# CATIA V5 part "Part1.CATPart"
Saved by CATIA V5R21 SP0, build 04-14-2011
Part number: Part1
Bounding box of the stored display mesh (mm): x -50 to 50, y -25 to 25, z -25 to 25
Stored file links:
  D:\CATIA V5R21 E-RESOURCES\CATIA-V5R21\catia-v5r21-prt\c16-catia-v5r20-prt\Sperical Joint-(Fig16-27)\CAT_V5R21_Part1.CATPart
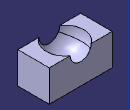
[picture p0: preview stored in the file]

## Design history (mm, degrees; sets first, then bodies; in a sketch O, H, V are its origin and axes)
Body1 (main body)
  Sketch1 on xy-plane, origin (0, 0, 0), H (1, 0, 0), V (0, 1, 0)
    line L1 (50, 25) -> (50, -25)
    line L2 (50, -25) -> (-50, -25)
    line L3 (-50, -25) -> (-50, 25)
    line L4 (-50, 25) -> (50, 25)
    length L4 = 100
    length L1 = 50
    vertical: L1 V, L3 V
    horizontal: L2 H, L4 H
    equidistance: L1 L3 O, L2 L4 O
  Pad1: profile Sketch1, direction (0, 0, 1), length 25, mirrored extent
  Sketch2 on end face of Pad1, origin (0, 0, 25), H (1, 0, 0), V (0, 1, 0)
    line L1 (0, -30) -> (0, 30)
    point P1 (0, -30)
    point P2 (0, 30)
    arc A1 centre (0, 0) radius 30 from (0, -30) to (0, 30) ccw
    point P3 (0, 30)
    radius A1 = 30
    coincidence: P1 V, P3 P2
    vertical: L1 V
  Groove1: profile Sketch2, axis Sketch2.L1, angle 360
